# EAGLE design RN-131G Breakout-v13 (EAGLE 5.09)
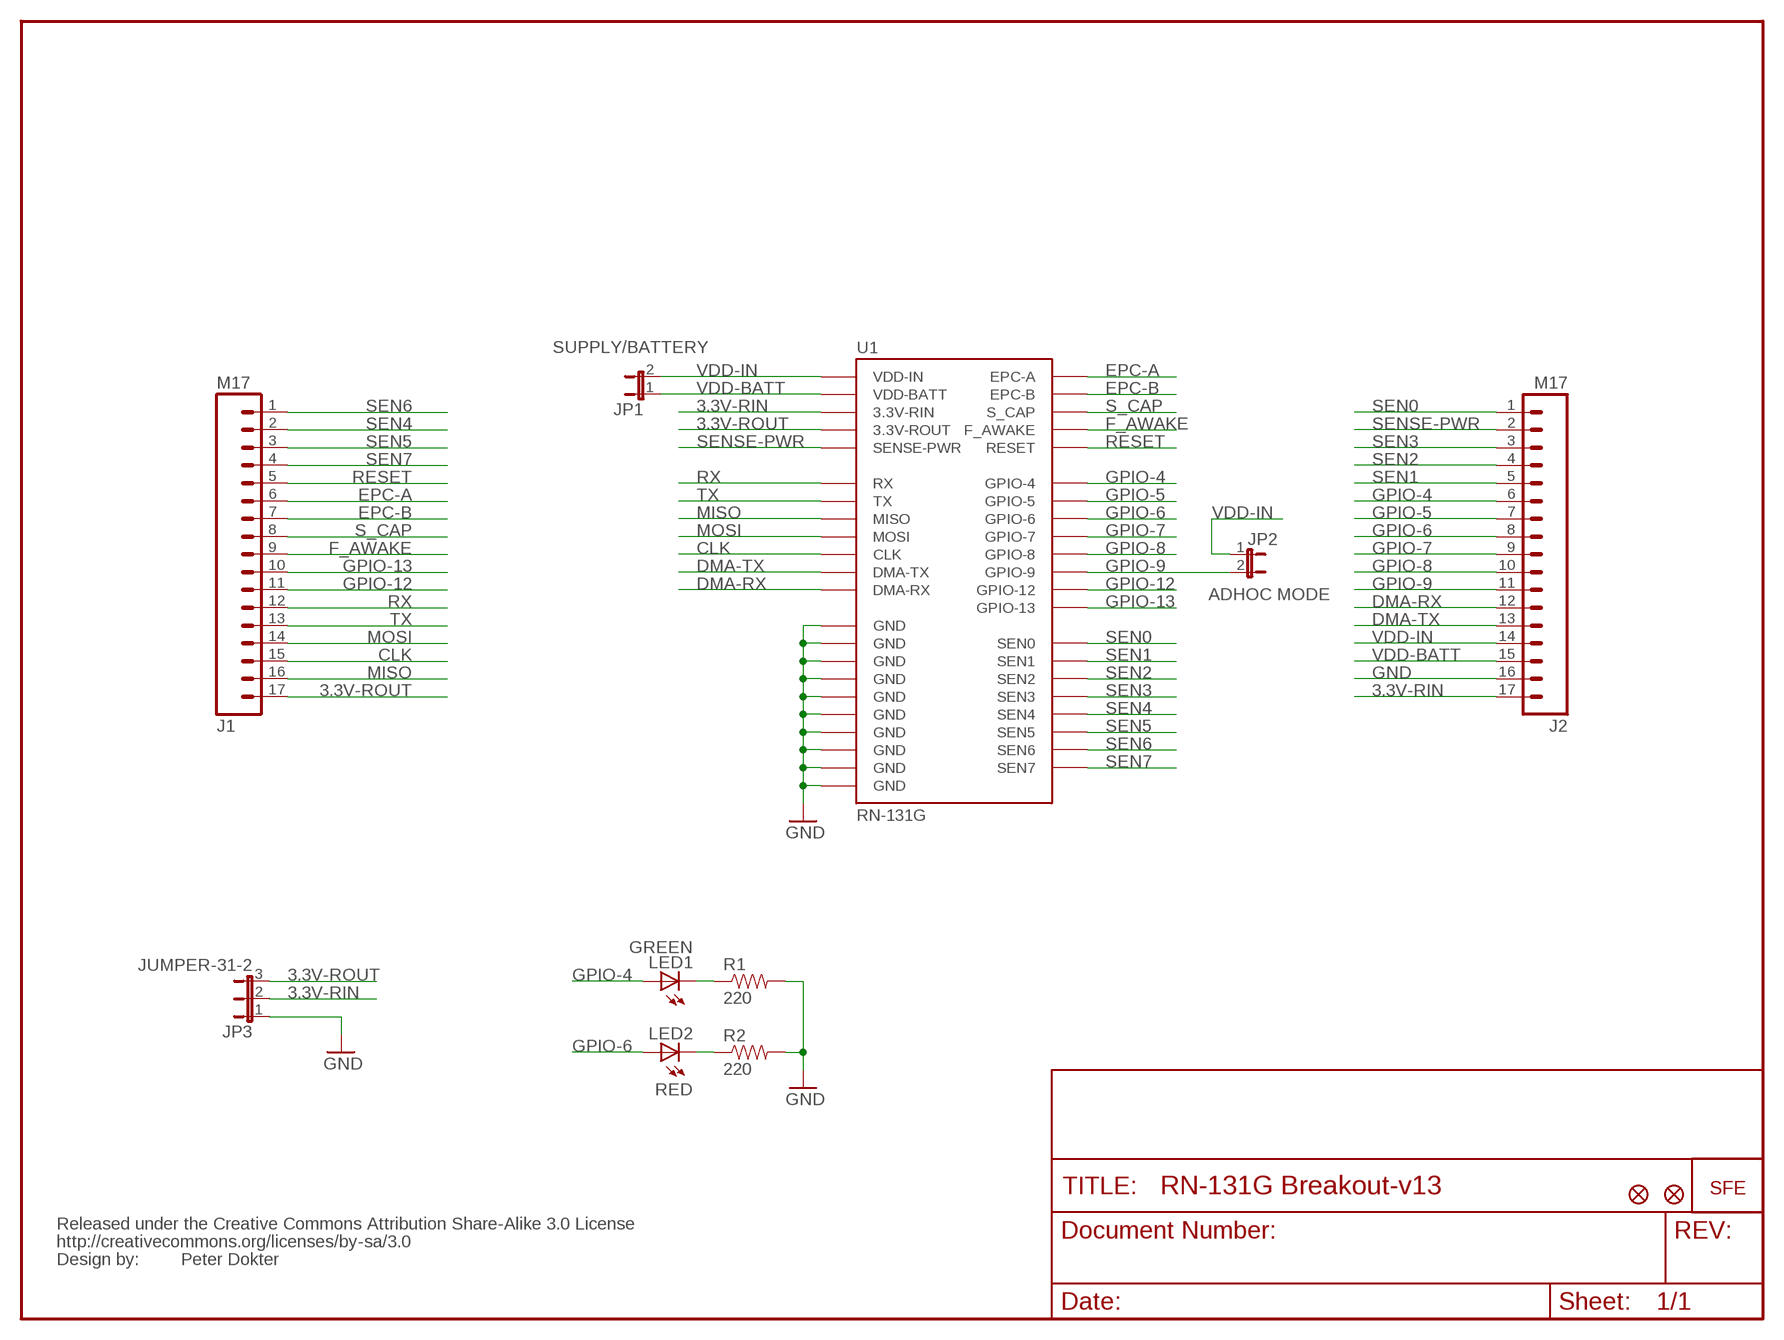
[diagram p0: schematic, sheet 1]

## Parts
J1  M17  [1X17]
J2  M17  [1X17]
JP1  JUMPER-2SMD-NO  [SJ_2S-NO]
JP2  JUMPER-2SMD-NO  [SJ_2S-NO]
JP3  JUMPER-31-2  [SJ_3_PASTE1&2]
LED1  GREEN  LED0603  [LED-0603]
LED2  RED  LED0603  [LED-0603]
R1  220  RESISTOR0402-RES  [0402-RES]
R2  220  RESISTOR0402-RES  [0402-RES]
U1  RN-131G  [RN-131G]
U$1  LOGO-SFENEW  [SFE-NEW-WEBLOGO]
U$2  FIDUCIAL1X2  [FIDUCIAL-1X2]
U$3  FIDUCIAL1X2  [FIDUCIAL-1X2]
U$4  CREATIVE_COMMONS  [CREATIVE_COMMONS]

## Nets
3.3V-RIN: J2.17 JP3.2 U1.P$18(3.3V-RIN)
3.3V-ROUT: J1.17 JP3.3 U1.P$17(3.3V-ROUT)
CLK: J1.15 U1.P$15(CLK)
DMA-RX: J2.12 U1.P$23(DMA-RX)
DMA-TX: J2.13 U1.P$22(DMA-TX)
EPC-A: J1.6 U1.P$6(EPC-A)
EPC-B: J1.7 U1.P$7(EPC-B)
F_AWAKE: J1.9 U1.P$9(F_AWAKE)
GND: J2.16 JP3.1 R1.2 R2.2 U1.P$19(GND) U1.P$36(GND) U1.P$37(GND) U1.P$38(GND) U1.P$39(GND) U1.P$40(GND) U1.P$41(GND) U1.P$42(GND) U1.P$43(GND) U1.P$44(GND)
GPIO-4: J2.6 LED1.A U1.P$29(GPIO-4)
GPIO-5: J2.7 U1.P$28(GPIO-5)
GPIO-6: J2.8 LED2.A U1.P$27(GPIO-6)
GPIO-7: J2.9 U1.P$26(GPIO-7)
GPIO-8: J2.10 U1.P$25(GPIO-8)
GPIO-9: J2.11 JP2.2 U1.P$24(GPIO-9)
GPIO-12: J1.11 U1.P$11(GPIO-12)
GPIO-13: J1.10 U1.P$10(GPIO-13)
MISO: J1.16 U1.P$16(MISO)
MOSI: J1.14 U1.P$14(MOSI)
N$1: LED2.C R2.1
N$2: LED1.C R1.1
RESET: J1.5 U1.P$5(RESET)
RX: J1.12 U1.P$12(RX)
S_CAP: J1.8 U1.P$8(S_CAP)
SEN0: J2.1 U1.P$34(SEN0)
SEN1: J2.5 U1.P$30(SEN1)
SEN2: J2.4 U1.P$31(SEN2)
SEN3: J2.3 U1.P$32(SEN3)
SEN4: J1.2 U1.P$2(SEN4)
SEN5: J1.3 U1.P$3(SEN5)
SEN6: J1.1 U1.P$1(SEN6)
SEN7: J1.4 U1.P$4(SEN7)
SENSE-PWR: J2.2 U1.P$33(SENSE-PWR)
TX: J1.13 U1.P$13(TX)
VDD-BATT: J2.15 JP1.1 U1.P$20(VDD-BATT)
VDD-IN: J2.14 JP1.2 JP2.1 U1.P$21(VDD-IN)

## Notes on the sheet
- SUPPLY/BATTERY
- ADHOC MODE
- Peter Dokter

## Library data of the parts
J1 J2 = SparkFun:M17
JP1 JP2 = SparkFun:JUMPER-2: Jumper
JP3 = SparkFun:JUMPER-3
LED1 LED2 = SparkFun:LED: LEDs
R1 R2 = SparkFun:RESISTOR: Resistor
U1 = SparkFun:RN-131G: Roving Netowrks WiFLy GSX Module
U$1 = SparkFun:LOGO-SFE: Spark Fun Electronics PCB Logo
U$2 U$3 = SparkFun:FIDUCIAL: Fiducial Alignment Points
U$4 = SparkFun:CREATIVE_COMMONS

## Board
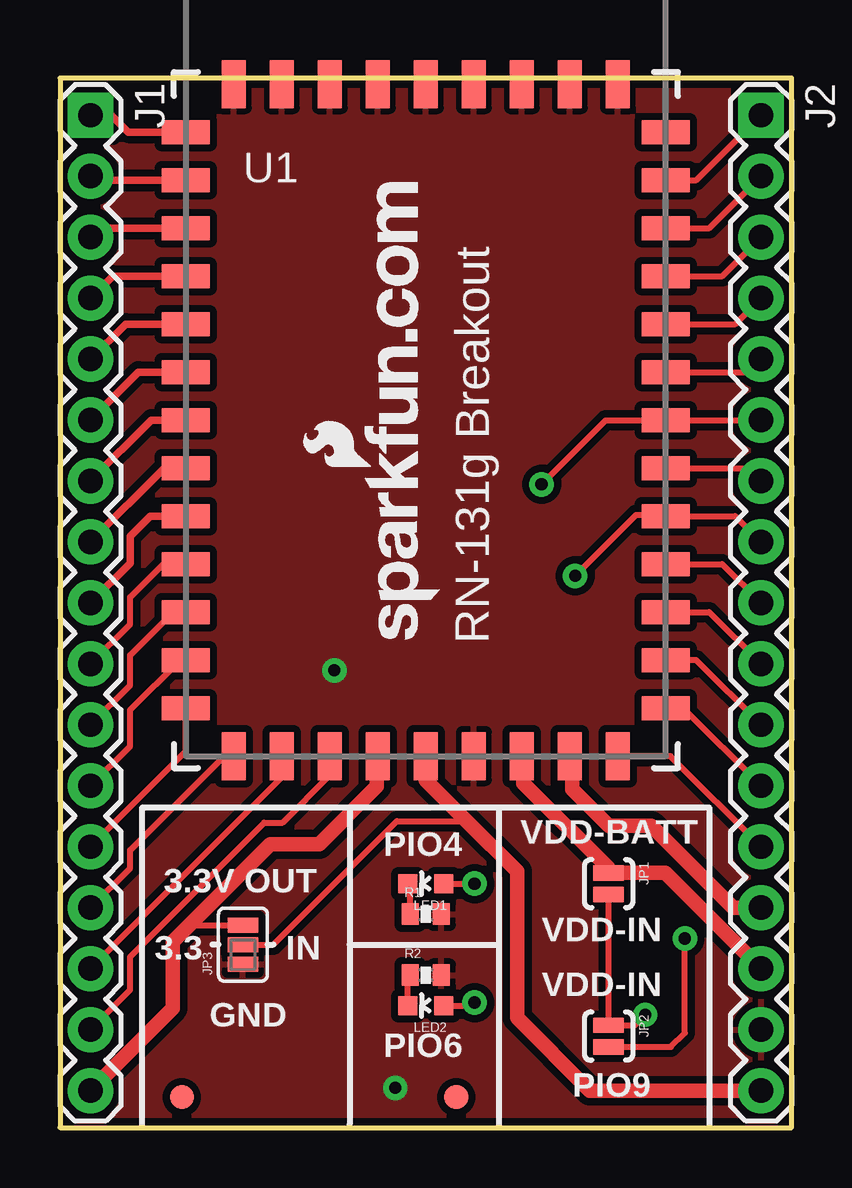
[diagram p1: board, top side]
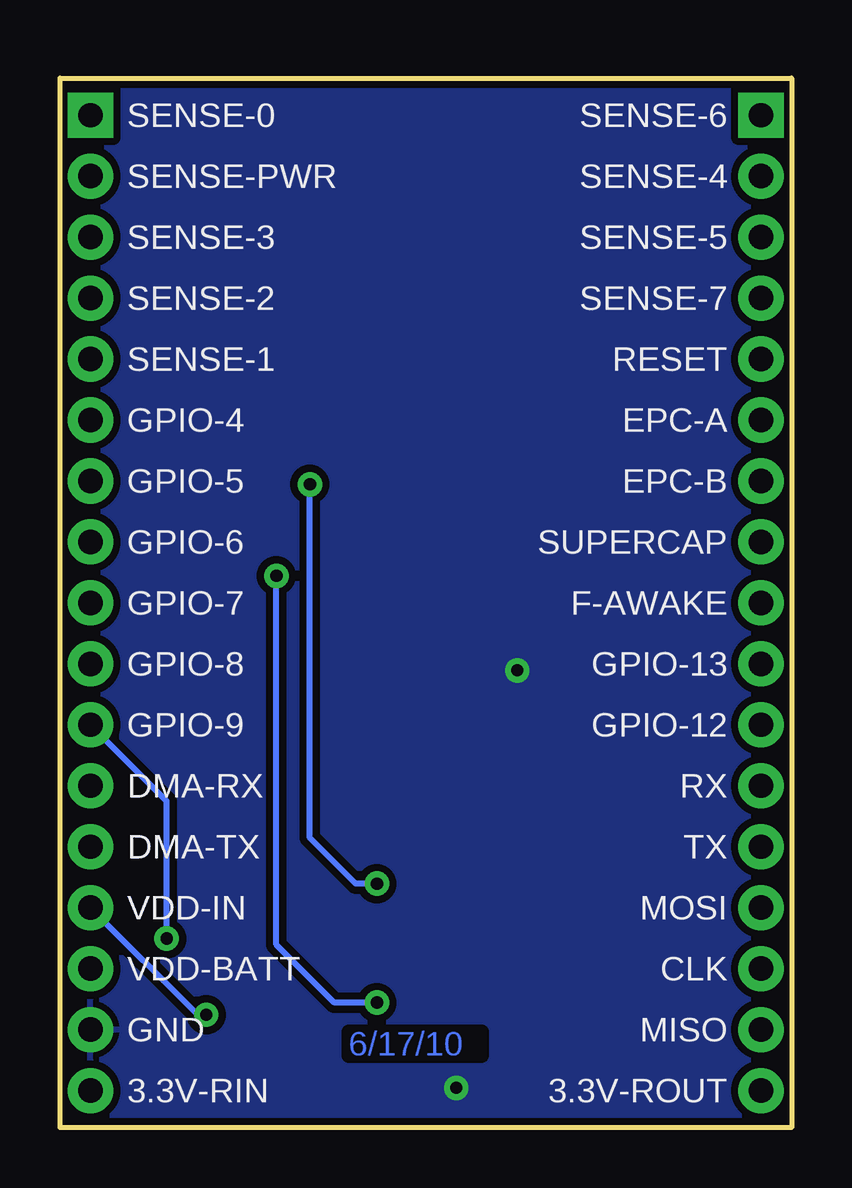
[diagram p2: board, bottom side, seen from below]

Size 30.48 x 43.72 mm. Coordinates in mm from the lower left corner, seen from the top.
Outline: 0,0 30.48,0 30.48,43.72 0,43.72 0,0
Copper layers (1*16): Top 0.0356mm / dielectric 1.5011mm / Bottom 0.0356mm
Design rules "default *": minimum track width 8mil, minimum drill 20mil, track to track 8mil, track to pad 8mil, pad to pad 8mil, via to via 8mil, smd to smd 8mil, copper to edge 8mil, drill to drill 8mil, minimum pad ring 12mil, minimum via ring 10mil, stop-mask expansion 4mil, vias tented up to drill 20mil, thermal gap 10mil

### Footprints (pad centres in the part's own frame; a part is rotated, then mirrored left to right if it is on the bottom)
1X17 = drill 1.016 pad 1.88 square: 1 0,0 | drill 1.016 pad 1.88 round: 2 2.54,0; 3 5.08,0; 4 7.62,0; 5 10.16,0; 6 12.7,0; 7 15.24,0; 8 17.78,0; 9 20.32,0; 10 22.86,0; 11 25.4,0; 12 27.94,0; 13 30.48,0; 14 33.02,0; 15 35.56,0; 16 38.1,0; 17 40.64,0
SJ_2S-NO = smd 0.635 x 1.27: 1 -0.45,0; 2 0.45,0
SJ_3_PASTE1&2 = smd 0.635 x 1.27: 1 -0.813,0; 2 0,0; 3 0.813,0
LED-0603 = smd 0.8 x 0.8: A 0,-0.75; C 0,0.75
0402-RES = smd 0.7 x 0.9: 1 -0.65,0; 2 0.65,0
RN-131G = smd 2 x 1: P$1 -10,11; P$2 -10,9; P$3 -10,7; P$4 -10,5; P$5 -10,3; P$6 -10,1; P$7 -10,-1; P$8 -10,-3; P$9 -10,-5; P$10 -10,-7; P$11 -10,-9; P$12 -10,-11; P$13 -10,-13; P$23 10,-13; P$24 10,-11; P$25 10,-9; P$26 10,-7; P$27 10,-5; P$28 10,-3; P$29 10,-1; P$30 10,1; P$31 10,3; P$32 10,5; P$33 10,7; P$34 10,9; P$35 10,11 | smd 1 x 2: P$14 -8,-15; P$15 -6,-15; P$16 -4,-15; P$17 -2,-15; P$18 0,-15; P$19 2,-15; P$20 4,-15; P$21 6,-15; P$22 8,-15; P$36 8,13; P$37 6,13; P$38 4,13; P$39 2,13; P$40 0,13; P$41 -2,13; P$42 -4,13; P$43 -6,13; P$44 -8,13
FIDUCIAL-1X2 = smd 1 x 1: 1 0,0

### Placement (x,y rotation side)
J1  1.27,42.18 270 top
J2  29.21,42.18 270 top
JP1  22.86,10.16 270 top
JP2  22.86,3.81 270 top
JP3  7.62,7.62 90 top
LED1  15.24,10.16 90 top
LED2  15.24,5.08 90 top
R1  15.24,8.89 0 top
R2  15.24,6.35 0 top
U1  15.24,30.48 0 top
U$1  15.83,20.34 90 top
U$2  5.08,1.27 0 top
U$3  16.51,1.27 0 top
U$4  13.97,11.43 0 top

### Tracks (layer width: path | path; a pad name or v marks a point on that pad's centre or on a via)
3.3V-RIN
  Top 0.254: 15.24,14.48 U1.P$18 | 16.95,12.76 14.03,12.76 8.89,7.62 JP3.2
  Top 0.61: J2.17 22.08,1.54 19.05,4.57 19.05,10.67 16.95,12.76 15.24,14.48 15.24,15.49
3.3V-ROUT
  Top 0.254: JP3.3 5.38,8.43 5.33,8.38
  Top 0.61: J1.17 4.7,4.97 4.7,7.75 5.33,8.38 8.76,11.81 10.79,11.81 13.21,14.22 13.21,15.45 U1.P$17
CLK
  Top 0.254: U1.P$15 9.24,14.59 J1.15
DMA-RX
  Top 0.254: U1.P$23 25.97,17.48 J2.12
DMA-TX
  Top 0.254: U1.P$22 25.43,15.48 J2.13
EPC-A
  Top 0.305: U1.P$6 3.27,31.48 J1.6
EPC-B
  Top 0.305: U1.P$7 3.81,29.48 J1.7
F_AWAKE
  Top 0.305: U1.P$9 3.76,25.48 2.92,24.64 2.92,23.51 J1.9
GND  (via drill 0.51)
  other vias: 13.97,1.65 11.43,19.05
  pour Top (isolate 0.305): 0,0 30.48,0 30.48,43.72 0,43.72
  pour Bottom (isolate 0.305): 0,0 30.48,0 30.48,43.72 0,43.72
GPIO-4  (via drill 0.51)
  Top 0.254: J2.6 U1.P$29 25.22,29.46 22.73,29.46 v20.07,26.8 | LED1.A v17.27,10.16
  Bottom 0.254: v17.27,10.16 18.16,10.16 20.07,12.06 v20.07,26.8
GPIO-5
  Top 0.254: U1.P$28 28.67,27.48 J2.7
GPIO-6  (via drill 0.51)
  Top 0.254: J2.8 28.13,25.48 U1.P$27 25.19,25.53 24,25.53 v21.46,22.99 | LED2.A 17.14,5.08 v17.27,5.21
  Bottom 0.254: v17.27,5.21 19.05,5.21 21.46,7.62 v21.46,22.99
GPIO-7
  Top 0.254: U1.P$26 27.59,23.48 J2.9
GPIO-8
  Top 0.254: U1.P$25 27.05,21.48 J2.10
GPIO-9  (via drill 0.51)
  Top 0.254: U1.P$24 26.51,19.48 J2.11 | JP2.2 25.46,3.36 26.04,3.94 v26.04,7.87
  Bottom 0.254: v26.04,7.87 26.04,13.61 J2.11
GPIO-12
  Top 0.254: U1.P$11 4.72,21.48 2.92,19.68 2.92,18.43 J1.11
GPIO-13
  Top 0.254: U1.P$10 4.3,23.48 2.92,22.1 2.92,20.97 J1.10
MISO
  Top 0.254: U1.P$16 11.24,14.67 9.27,12.7 8.51,12.7 2.92,7.11 2.92,5.73 J1.16
MOSI
  Top 0.254: U1.P$14 6.84,15.48 2.92,11.56 2.92,10.81 J1.14
N$1
  Top 0.254: LED2.C 14.49,6.25 R2.1
N$2
  Top 0.254: R1.1 14.59,10.06 LED1.C
RESET
  Top 0.305: U1.P$5 2.73,33.48 J1.5
RX
  Top 0.254: U1.P$12 5,19.48 2.92,17.4 2.92,15.89 J1.12
S_CAP
  Top 0.305: U1.P$8 4.35,27.48 J1.8
SEN0
  Top 0.254: U1.P$34 26.51,39.48 J2.1
SEN1
  Top 0.254: U1.P$30 28.67,31.48 J2.5
SEN2
  Top 0.254: U1.P$31 28.13,33.48 J2.4
SEN3
  Top 0.254: U1.P$32 27.59,35.48 J2.3
SEN4
  Top 0.305: U1.P$2 1.43,39.48 J1.2
SEN5
  Top 0.305: U1.P$3 1.65,37.48 J1.3
SEN6
  Top 0.305: U1.P$1 2.84,41.48 2.16,42.16 1.29,42.16 J1.1
SEN7
  Top 0.305: U1.P$4 2.19,35.48 J1.4
SENSE-PWR
  Top 0.254: U1.P$33 27.05,37.48 J2.2
TX
  Top 0.254: U1.P$13 5.24,15.67 J1.13
VDD-BATT
  Top 0.61: J2.15 25.22,10.61 JP1.1 22.86,10.79 19.3,14.35 19.3,15.42 U1.P$20
VDD-IN  (via drill 0.51)
  Top 0.254: v24.38,4.7 23.95,4.26 JP2.1 JP1.2
  Top 0.61: J2.14 28.05,9.16 24.64,12.57 22.86,12.57 21.34,14.1 21.34,15.38 U1.P$21
  Bottom 0.254: v24.38,4.7 24.75,4.7 J2.14

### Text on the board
Bottom: 6/17/10
tPlace: RN-131g Breakout | VDD-BATT | PIO4 | 3.3V OUT | VDD-IN | 3.3 | IN | VDD-IN | GND | PIO6 | PIO9
bPlace: SENSE-6 | SENSE-0 | SENSE-4 | SENSE-PWR | SENSE-5 | SENSE-3 | SENSE-7 | SENSE-2 | RESET | SENSE-1 | EPC-A | GPIO-4 | EPC-B | GPIO-5 | SUPERCAP | GPIO-6 | F-AWAKE | GPIO-7 | GPIO-13 | GPIO-8 | GPIO-12 | GPIO-9 | RX | DMA-RX | TX | DMA-TX | MOSI | VDD-IN | CLK | VDD-BATT | MISO | GND | 3.3V-ROUT | 3.3V-RIN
